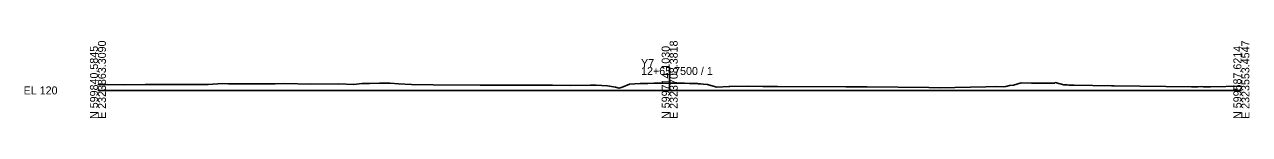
# Model space of a CAD drawing. Extents: x -26 to 3203, y -10 to 1017.
# Drawn here: x 2774.3 to 3202.8, y -9.7 to 17.3 of the extents above; entities that cross this region are included whole.
import ezdxf

# ---------------------------------------------------------------- set-up
doc = ezdxf.new("R2010")
doc.units = 0
for name, color, linetype in [('Exist CMT Pavement', 7, 'Continuous'), ('Exist Cross Section Cell', 7, 'Continuous'), ('Exist XS Center Line Elevation Label', 7, 'Continuous'), ('Exist XS Ground Line', 7, 'Continuous'), ('Prop XS Earthwork Shape', 7, 'Continuous')]:
    doc.layers.add(name, color=color, linetype=linetype)

msp = doc.modelspace()

# ---------------------------------------------------------------- linework, layer by layer
at = {"layer": 'Exist CMT Pavement'}
msp.add_lwpolyline([(3000, 2.58), (3000, 2.68), (3000.1, 2.68), (3000.1, 2.58)], dxfattribs=at)
at = {"layer": 'Exist Cross Section Cell'}
for p, q in [((3000, 0), (3000, 8.2)), ((2800, 0), (3000, 0)), ((3000, 0), (3200, 0))]:
    msp.add_line(p, q, dxfattribs=at)
at = {"layer": 'Exist XS Ground Line'}
msp.add_lwpolyline([(2800, 2.01), (2803.22, 2.05), (2809.25, 2), (2816.56, 2.02), (2833.45, 2.04), (2838.59, 2.12), (2843.54, 2.38), (2845.65, 2.26), (2846.59, 2.26), (2849.09, 2.28), (2856.18, 2.26), (2857.84, 2.34), (2862.03, 2.28), (2865.3, 2.41), (2874.51, 2.18), (2884.3, 2.29), (2889.52, 2.1), (2892.26, 2.43), (2895.01, 2.45), (2898.46, 2.51), (2902.18, 2.5), (2905.09, 2.33), (2909.73, 2.12), (2917.22, 2.01), (2933.72, 1.85), (2937.36, 1.83), (2941.9, 1.88), (2958.97, 1.79), (2965.18, 1.72), (2972.28, 1.84), (2974.3, 1.81), (2976.27, 1.73), (2978.22, 1.62), (2981.1, 1.08), (2982.31, 0.82), (2983.78, 1.31), (2985.99, 2.13), (2989.73, 2.41), (2990.23, 2.44), (2991.36, 2.46), (2991.77, 2.46), (2992.31, 2.47), (2994.46, 2.5), (2995.4, 2.51), (2997.15, 2.55), (2997.79, 2.55), (3000, 2.58), (3001.18, 2.57), (3002.52, 2.55), (3003.11, 2.54), (3004.63, 2.49), (3005.2, 2.48), (3006.97, 2.44), (3007.89, 2.41), (3009.78, 2.37), (3010.14, 2.34), (3010.79, 2.3), (3011.71, 2.24), (3013.23, 2.1), (3015.99, 1.3), (3016.58, 1.12), (3020.65, 1.32), (3021.05, 1.33), (3027.7, 1.45), (3032.58, 1.41), (3034.45, 1.38), (3037.77, 1.36), (3061.57, 1.25), (3064.97, 1.23), (3069.12, 1.2), (3090.72, 1), (3094.44, 0.94), (3110.62, 1.25), (3114.05, 1.32), (3116.71, 1.31), (3117.59, 1.42), (3118.93, 1.68), (3120.33, 1.85), (3122.95, 2.68), (3126.53, 2.5), (3131.05, 2.48), (3133.5, 2.49), (3134.65, 2.48), (3134.86, 2.73), (3137.9, 1.94), (3139.11, 1.92), (3139.67, 1.82), (3141.48, 1.87), (3154.56, 1.59), (3155.55, 1.59), (3182.5, 1.31), (3184.77, 1.31), (3185.98, 1.33), (3186.71, 1.26), (3189.23, 1.29), (3200, 1.49)], dxfattribs=at)
at = {"layer": 'Prop XS Earthwork Shape'}
msp.add_lwpolyline([(3000, 2.58), (3000.1, 2.58), (3000.1, 2.68), (3000, 2.68)], close=True, dxfattribs=at)

# ---------------------------------------------------------------- texts
at = {"layer": 'Exist Cross Section Cell'}
for s, p in [('E 2323863.3090', (2802.8, -10)), ('E 2323708.3818', (3002.8, -10)), ('E 2323553.4547', (3202.8, -10)), ('N 599840.5845', (2800, -10)), ('N 599714.1030', (3000, -10)), ('N 599587.6214', (3200, -10))]:
    msp.add_text(s, height=2.8, rotation=90, dxfattribs=at).set_placement(p)
for s, p in [('Y7', (2990, 8.2)), ('12+65.7500 / 1', (2990, 5.4)), ('EL 120', (2774, -1.4))]:
    msp.add_text(s, height=2.8, dxfattribs=at).set_placement(p)
at = {"layer": 'Exist XS Center Line Elevation Label'}
msp.add_text('122.58', height=0.2, dxfattribs=at).set_placement((2999.6, 0.58))

doc.saveas('drawing.dxf')
